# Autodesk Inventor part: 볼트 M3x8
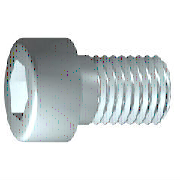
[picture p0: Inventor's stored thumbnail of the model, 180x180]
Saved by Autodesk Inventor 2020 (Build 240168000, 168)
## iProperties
Created: 2012-02
Part Number: 볼트 M3x8
Material: 강철, 연강
Description: 6각 소켓 머리 캡 나사
Document SubType Name: Modeling
Standard: ISO 4762
Designer: mdu-01
Standard Revision: Fourth edition 2004-03-01
Standards Organization: ISO
Language: ko-KR
Size Designation: M3 x 8
Categories: <MemberInstance><Categories><Category DisplayName="조임쇠" InternalName="e4da775c-781d-43d5-af7c-5136215cf5a6" Mnemonic="FSTN"><Category DisplayName="볼트" InternalN
Density: 7.86 g/cm^3
Appearance: 강철
Mass: 0.929844 g
Surface Area: 1.83001 cm^2
Volume: 0.118301 cm^3
IsCustomPart: 1
Author: mdu-01
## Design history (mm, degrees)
sketch "스케치1"
  geometry: L1 (-0.867, 0)-(8, 0); L2 (8, 0)-(8, 1.5); L3 (8, 1.5)-(1.25, 1.5); L4 (1.25, 1.5)-(0.943, 1.5); L5 (0.943, 1.5)-(0, 1.5); L6 (0, 1.5)-(0, 2.75); L7 (0, 2.75)-(-3, 2.75); L8 (-3, 2.75)-(-3, 1.443); L9 (-3, 1.443)-(-1.7, 1.443); L10 (-1.7, 1.443)-(-0.867, 0); L11 (-5.2, 0)-(10.2, 0) reference; L12 (0, -0.55)-(0, 3.3) reference; L13 (1.25, 1.5)-(0, 1.5)
  constraints: 22 end point, 6 parallel, 2 collinear, 2 perpendicular, 1 horizontal, 1 point on line
  dimensions: "d1" = 6.75 distance from line of L3.end L2 (= GEL); "d2" = 0.30683 distance of L4.end L3.end (computed from GAL); "d3" = 3 distance between parallel lines of L8 L6 (= KOH); "d4" = 1.3 distance of L8.end L9.end (= INTI); "d5" = 60 deg angle of L10 L1; "d6" = 3 diameter of L3 L1 (= GD); "d7" = 3 diameter of L5 L1 (= BDM); "d8" = 2.88675 diameter of L9 L1 (= 1.1547 x SW); "d9" = 5.5 diameter of L7 L1 (= KOD); "d26" = 8 distance between parallel lines of L12 L2 (= NLG)
revolve "본체" sketch "스케치1" stored, may be unused: angle "d10" = 90 deg
sketch "스케치2"
  geometry: L1 (0, -3.85)-(0, 3.85) reference; L2 (-3.85, 0)-(3.85, 0) reference; L3 (1.443, 0)-(0.722, -1.25); L4 (0.722, -1.25)-(-0.722, -1.25); L5 (-0.722, -1.25)-(-1.443, 0); L6 (-1.443, 0)-(-0.722, 1.25); L7 (-0.722, 1.25)-(0.722, 1.25); L8 (0.722, 1.25)-(1.443, 0); 2 further points
  constraints: 12 end point, 1 coincident, 1 horizontal alignment, 1 point on line, 12 other
extrude "슬롯" join sketch "스케치2" stored distance "d11" = 10; taper "d12" = 0 deg
workplane "Work Plane1"
fillet "Fillet2" dims "d30" = 0.1 (= R)
body "Solid1"
fillet "모깎기1" dims "d17" = 0.3 (= RR)
feature "스레드" dims "d13" = 6.75 (= GEL), "d14" = 0
chamfer "모따기1" distance "d15" = 0.30673 (= -0.5 x SPD + 0.5 x GD); stored, may be unused: second distance "d16" = 0.30673 (= GUL), angle "d27" = 45 deg
other parameters: "GD" = 3 [user parameter; used in 2 equation terms], "NLG" = 8 [user parameter; used in 1 equation term], "GEL" = 6.75 [user parameter; used in 2 equation terms], "KOD" = 5.5 [user parameter; used in 1 equation term], "KOH" = 3 [user parameter; used in 1 equation term], "INTI" = 1.3 [user parameter; used in 1 equation term], "GAL" = 0.30673 (= 0.61345 x PTC) [user parameter; used in 1 equation term], "GUL" = 0.30673 (= 0.61345 x PTC) [user parameter; used in 1 equation term], "BDM" = 3 (= NND) [user parameter; used in 1 equation term], "SW" = 2.5 [user parameter; used in 2 equation terms], "RR" = 0.3 [user parameter; used in 1 equation term], "SPD" = 2.38655 (= NND - 1.2269 x PTC) [user parameter; used in 1 equation term], "d19" = 0, "d28" = 0, "d29" = 0, "R" = 0.1 [user parameter; used in 1 equation term], "TOA" = 30 deg [user parameter], "GD1" = 2.38655 (= THREADDIA - 1.2269 x PTC) [user parameter], "THREADDIA" = 3 [user parameter; used in 1 equation term], "FAWI" = 45 deg [user parameter], "PTC" = 0.5 [user parameter; used in 5 equation terms], "NND" = 3 [user parameter; used in 2 equation terms], "E0" = 2.8875 (= 1.155 x SW) [user parameter]
